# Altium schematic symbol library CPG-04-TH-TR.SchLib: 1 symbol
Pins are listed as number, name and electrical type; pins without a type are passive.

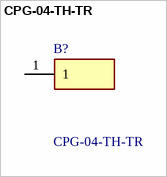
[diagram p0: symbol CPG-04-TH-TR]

## CPG-04-TH-TR
designator B?
120 gf Initial Operating Force, 85 gf Mid Compression Operating Force, Spring Loaded, Gold Plated, Through Hole, Pogo Pin; Manufacturer_Name: Same Sky; Geometry.Height: 6.1mm
footprint CPG04THTR
pins: 1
